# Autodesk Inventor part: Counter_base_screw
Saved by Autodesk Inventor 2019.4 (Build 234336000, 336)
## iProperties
Created: 2019-10
Part Number: Counter_base_screw
Material: Generic
Document SubType Name: Modeling
Designer: Administrator
Density: 1 g/cm^3
Appearance: Default
Title: Counter_base_screw
Author: Administrator
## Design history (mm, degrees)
feature "Body1"
feature "Body3"
body "Solid1"
body "Solid2"
